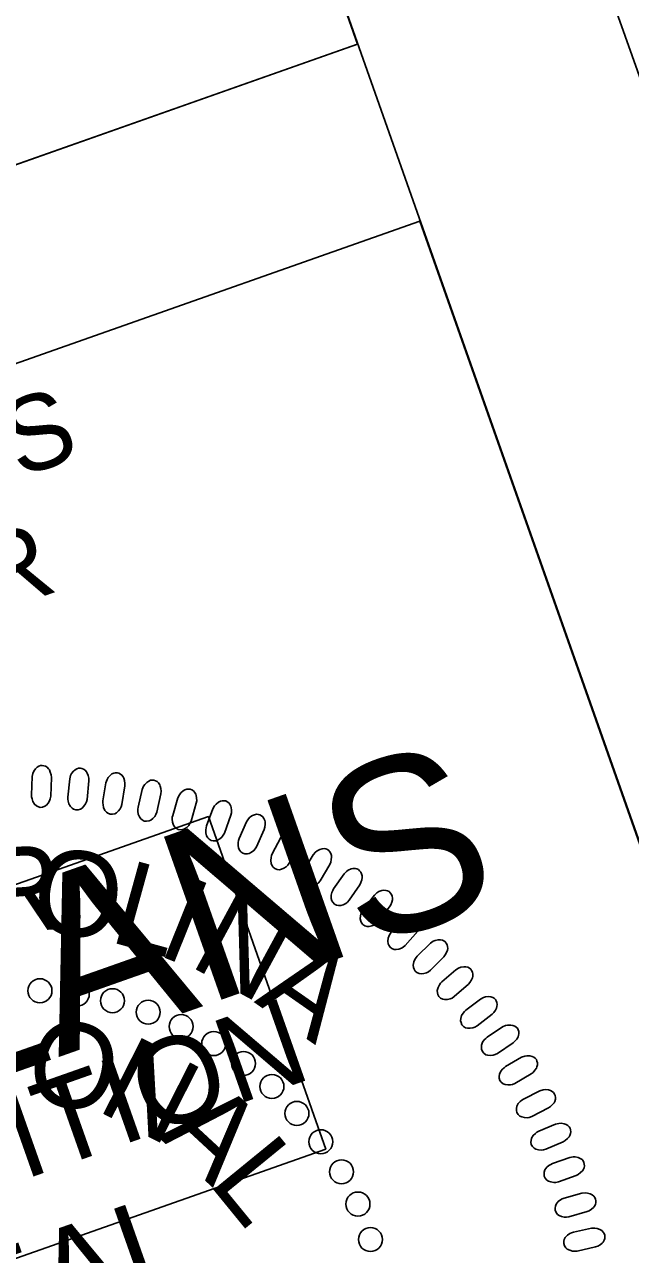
# Model space of a CAD drawing. Extents: x 473817 to 475769, y 501102 to 502694.
# Drawn here: x 475382.8 to 475423.1, y 502563 to 502645 of the extents above; entities that cross this region are included whole.
import ezdxf

# ---------------------------------------------------------------- set-up
doc = ezdxf.new("R2010")
doc.units = 0
for name, color, linetype in [('Sheet PE Seal Cell', 7, 'Continuous'), ('Sheet Plan CELL', 7, 'Continuous'), ('Sheet Plot Border Outside CELL', 7, 'Continuous'), ('Sheet Sticker Incomplete CELL', 7, 'Continuous')]:
    doc.layers.add(name, color=color, linetype=linetype)

msp = doc.modelspace()

# ---------------------------------------------------------------- linework, layer by layer
at = {"layer": 'Sheet PE Seal Cell'}
for points in [[(475383.217, 502593.623), (475383.264, 502594.848), (475383.31, 502595.066), (475383.367, 502595.204), (475383.486, 502595.369), (475383.588, 502595.475), (475383.703, 502595.55), (475383.809, 502595.586), (475383.921, 502595.602), (475384.032, 502595.578), (475384.151, 502595.543), (475384.253, 502595.479), (475384.354, 502595.375), (475384.411, 502595.294), (475384.472, 502595.142), (475384.526, 502594.96), (475384.542, 502594.8), (475384.501, 502593.543), (475384.472, 502593.375), (475384.422, 502593.237), (475384.326, 502593.082), (475384.209, 502592.946), (475384.109, 502592.87), (475383.949, 502592.817), (475383.799, 502592.802), (475383.651, 502592.848), (475383.548, 502592.901), (475383.425, 502593.006), (475383.313, 502593.18), (475383.252, 502593.362), (475383.227, 502593.493)], [(475385.642, 502593.487), (475385.765, 502594.708), (475385.825, 502594.922), (475385.891, 502595.056), (475386.02, 502595.213), (475386.127, 502595.312), (475386.247, 502595.38), (475386.355, 502595.41), (475386.469, 502595.418), (475386.578, 502595.386), (475386.694, 502595.345), (475386.792, 502595.275), (475386.886, 502595.165), (475386.938, 502595.08), (475386.99, 502594.924), (475387.031, 502594.74), (475387.038, 502594.578), (475386.918, 502593.327), (475386.878, 502593.161), (475386.819, 502593.026), (475386.714, 502592.877), (475386.588, 502592.749), (475386.484, 502592.68), (475386.321, 502592.636), (475386.17, 502592.632), (475386.026, 502592.686), (475385.927, 502592.746), (475385.811, 502592.858), (475385.709, 502593.039), (475385.66, 502593.224), (475385.644, 502593.356)], [(475387.982, 502593.236), (475388.182, 502594.446), (475388.255, 502594.656), (475388.329, 502594.786), (475388.468, 502594.934), (475388.581, 502595.027), (475388.706, 502595.087), (475388.815, 502595.11), (475388.929, 502595.111), (475389.036, 502595.073), (475389.149, 502595.024), (475389.243, 502594.948), (475389.33, 502594.833), (475389.376, 502594.744), (475389.418, 502594.586), (475389.447, 502594.398), (475389.444, 502594.238), (475389.246, 502592.996), (475389.196, 502592.833), (475389.129, 502592.702), (475389.015, 502592.56), (475388.881, 502592.44), (475388.772, 502592.377), (475388.607, 502592.344), (475388.457, 502592.349), (475388.316, 502592.412), (475388.22, 502592.479), (475388.111, 502592.598), (475388.021, 502592.785), (475387.984, 502592.973), (475387.976, 502593.106)], [(475390.317, 502592.803), (475390.593, 502593.998), (475390.679, 502594.203), (475390.761, 502594.327), (475390.908, 502594.468), (475391.028, 502594.553), (475391.155, 502594.605), (475391.266, 502594.62), (475391.38, 502594.615), (475391.485, 502594.57), (475391.594, 502594.514), (475391.683, 502594.433), (475391.763, 502594.311), (475391.803, 502594.22), (475391.835, 502594.059), (475391.853, 502593.871), (475391.839, 502593.711), (475391.563, 502592.484), (475391.503, 502592.324), (475391.428, 502592.199), (475391.305, 502592.063), (475391.165, 502591.952), (475391.052, 502591.896), (475390.885, 502591.873), (475390.735, 502591.888), (475390.599, 502591.96), (475390.508, 502592.032), (475390.406, 502592.158), (475390.328, 502592.35), (475390.303, 502592.54), (475390.303, 502592.673)], [(475392.627, 502592.267), (475392.977, 502593.442), (475393.075, 502593.643), (475393.166, 502593.762), (475393.321, 502593.892), (475393.446, 502593.969), (475393.576, 502594.014), (475393.688, 502594.022), (475393.801, 502594.009), (475393.903, 502593.958), (475394.008, 502593.895), (475394.092, 502593.808), (475394.164, 502593.682), (475394.199, 502593.589), (475394.22, 502593.426), (475394.226, 502593.237), (475394.202, 502593.078), (475393.85, 502591.871), (475393.78, 502591.715), (475393.697, 502591.594), (475393.566, 502591.467), (475393.419, 502591.365), (475393.302, 502591.316), (475393.135, 502591.304), (475392.986, 502591.328), (475392.854, 502591.408), (475392.768, 502591.486), (475392.675, 502591.618), (475392.609, 502591.815), (475392.596, 502592.006), (475392.604, 502592.139)], [(475394.884, 502591.561), (475395.308, 502592.713), (475395.418, 502592.906), (475395.516, 502593.019), (475395.68, 502593.14), (475395.809, 502593.209), (475395.941, 502593.245), (475396.053, 502593.246), (475396.166, 502593.226), (475396.264, 502593.169), (475396.366, 502593.099), (475396.443, 502593.007), (475396.507, 502592.877), (475396.536, 502592.782), (475396.547, 502592.618), (475396.541, 502592.429), (475396.508, 502592.272), (475396.081, 502591.09), (475396.001, 502590.938), (475395.911, 502590.822), (475395.772, 502590.704), (475395.618, 502590.611), (475395.499, 502590.57), (475395.331, 502590.568), (475395.184, 502590.601), (475395.057, 502590.69), (475394.976, 502590.773), (475394.892, 502590.911), (475394.838, 502591.11), (475394.837, 502591.303), (475394.854, 502591.435)], [(475397.058, 502590.722), (475397.554, 502591.845), (475397.676, 502592.031), (475397.78, 502592.138), (475397.951, 502592.248), (475398.085, 502592.309), (475398.219, 502592.337), (475398.331, 502592.331), (475398.442, 502592.304), (475398.536, 502592.24), (475398.634, 502592.165), (475398.706, 502592.068), (475398.761, 502591.934), (475398.784, 502591.837), (475398.785, 502591.673), (475398.767, 502591.485), (475398.723, 502591.33), (475398.223, 502590.177), (475398.134, 502590.031), (475398.037, 502589.921), (475397.89, 502589.812), (475397.732, 502589.729), (475397.61, 502589.695), (475397.442, 502589.703), (475397.297, 502589.746), (475397.177, 502589.843), (475397.101, 502589.93), (475397.025, 502590.073), (475396.984, 502590.276), (475396.995, 502590.467), (475397.02, 502590.598)], [(475399.267, 502589.706), (475399.831, 502590.795), (475399.965, 502590.972), (475400.076, 502591.073), (475400.253, 502591.171), (475400.39, 502591.224), (475400.526, 502591.243), (475400.638, 502591.231), (475400.747, 502591.197), (475400.837, 502591.127), (475400.93, 502591.046), (475400.995, 502590.945), (475401.042, 502590.808), (475401.058, 502590.709), (475401.049, 502590.546), (475401.02, 502590.359), (475400.966, 502590.207), (475400.394, 502589.088), (475400.297, 502588.948), (475400.193, 502588.844), (475400.04, 502588.744), (475399.876, 502588.671), (475399.752, 502588.645), (475399.586, 502588.664), (475399.444, 502588.715), (475399.329, 502588.819), (475399.26, 502588.912), (475399.192, 502589.059), (475399.165, 502589.264), (475399.187, 502589.455), (475399.221, 502589.584)], [(475401.368, 502588.595), (475401.999, 502589.646), (475402.145, 502589.815), (475402.261, 502589.908), (475402.445, 502589.996), (475402.585, 502590.04), (475402.722, 502590.05), (475402.832, 502590.03), (475402.939, 502589.99), (475403.024, 502589.915), (475403.111, 502589.828), (475403.171, 502589.723), (475403.209, 502589.583), (475403.219, 502589.484), (475403.199, 502589.321), (475403.158, 502589.137), (475403.095, 502588.988), (475402.454, 502587.907), (475402.348, 502587.773), (475402.238, 502587.677), (475402.079, 502587.587), (475401.911, 502587.524), (475401.786, 502587.506), (475401.621, 502587.535), (475401.482, 502587.595), (475401.375, 502587.706), (475401.311, 502587.803), (475401.253, 502587.954), (475401.238, 502588.161), (475401.273, 502588.35), (475401.314, 502588.476)], [(475403.351, 502587.362), (475404.048, 502588.371), (475404.203, 502588.531), (475404.325, 502588.616), (475404.514, 502588.692), (475404.656, 502588.727), (475404.793, 502588.729), (475404.902, 502588.703), (475405.006, 502588.655), (475405.087, 502588.575), (475405.168, 502588.483), (475405.221, 502588.374), (475405.25, 502588.233), (475405.254, 502588.133), (475405.224, 502587.971), (475405.172, 502587.79), (475405.1, 502587.646), (475404.392, 502586.607), (475404.278, 502586.481), (475404.161, 502586.391), (475403.997, 502586.311), (475403.825, 502586.259), (475403.7, 502586.249), (475403.537, 502586.288), (475403.402, 502586.357), (475403.302, 502586.475), (475403.245, 502586.575), (475403.196, 502586.729), (475403.194, 502586.937), (475403.24, 502587.123), (475403.29, 502587.247)], [(475405.319, 502585.992), (475406.077, 502586.956), (475406.243, 502587.106), (475406.37, 502587.183), (475406.563, 502587.247), (475406.707, 502587.273), (475406.844, 502587.267), (475406.952, 502587.233), (475407.052, 502587.18), (475407.128, 502587.095), (475407.203, 502586.997), (475407.248, 502586.886), (475407.269, 502586.742), (475407.267, 502586.642), (475407.227, 502586.483), (475407.163, 502586.305), (475407.082, 502586.166), (475406.311, 502585.174), (475406.189, 502585.055), (475406.067, 502584.973), (475405.898, 502584.903), (475405.723, 502584.862), (475405.597, 502584.859), (475405.437, 502584.909), (475405.308, 502584.986), (475405.215, 502585.11), (475405.163, 502585.214), (475405.125, 502585.371), (475405.135, 502585.578), (475405.194, 502585.761), (475405.251, 502585.881)], [(475407.19, 502584.478), (475408.008, 502585.393), (475408.182, 502585.531), (475408.313, 502585.601), (475408.51, 502585.653), (475408.655, 502585.67), (475408.793, 502585.654), (475408.897, 502585.614), (475408.994, 502585.554), (475409.064, 502585.465), (475409.133, 502585.363), (475409.172, 502585.249), (475409.183, 502585.104), (475409.175, 502585.005), (475409.125, 502584.848), (475409.05, 502584.675), (475408.96, 502584.541), (475408.129, 502583.599), (475407.999, 502583.488), (475407.872, 502583.413), (475407.699, 502583.355), (475407.523, 502583.325), (475407.397, 502583.33), (475407.24, 502583.39), (475407.115, 502583.475), (475407.03, 502583.604), (475406.985, 502583.711), (475406.957, 502583.87), (475406.981, 502584.077), (475407.051, 502584.255), (475407.115, 502584.372)], [(475408.927, 502582.882), (475409.8, 502583.744), (475409.983, 502583.871), (475410.119, 502583.932), (475410.318, 502583.971), (475410.465, 502583.978), (475410.601, 502583.955), (475410.702, 502583.909), (475410.795, 502583.842), (475410.86, 502583.749), (475410.922, 502583.642), (475410.953, 502583.526), (475410.956, 502583.382), (475410.941, 502583.283), (475410.882, 502583.129), (475410.795, 502582.962), (475410.698, 502582.833), (475409.808, 502581.945), (475409.672, 502581.843), (475409.541, 502581.777), (475409.365, 502581.729), (475409.186, 502581.71), (475409.061, 502581.723), (475408.908, 502581.793), (475408.789, 502581.886), (475408.713, 502582.02), (475408.675, 502582.13), (475408.656, 502582.29), (475408.693, 502582.494), (475408.774, 502582.668), (475408.846, 502582.78)], [(475410.569, 502581.169), (475411.495, 502581.975), (475411.685, 502582.09), (475411.824, 502582.143), (475412.026, 502582.169), (475412.173, 502582.167), (475412.307, 502582.135), (475412.405, 502582.083), (475412.494, 502582.011), (475412.552, 502581.913), (475412.608, 502581.803), (475412.632, 502581.686), (475412.625, 502581.54), (475412.605, 502581.443), (475412.536, 502581.294), (475412.44, 502581.131), (475412.334, 502581.01), (475411.39, 502580.18), (475411.248, 502580.085), (475411.113, 502580.028), (475410.934, 502579.991), (475410.755, 502579.983), (475410.63, 502580.005), (475410.482, 502580.084), (475410.369, 502580.184), (475410.301, 502580.323), (475410.27, 502580.434), (475410.262, 502580.596), (475410.312, 502580.797), (475410.403, 502580.966), (475410.482, 502581.073)], [(475412.163, 502579.278), (475413.138, 502580.023), (475413.335, 502580.126), (475413.478, 502580.17), (475413.68, 502580.184), (475413.827, 502580.174), (475413.958, 502580.133), (475414.053, 502580.074), (475414.137, 502579.997), (475414.189, 502579.896), (475414.238, 502579.782), (475414.254, 502579.663), (475414.238, 502579.519), (475414.212, 502579.423), (475414.133, 502579.278), (475414.028, 502579.122), (475413.914, 502579.007), (475412.921, 502578.238), (475412.772, 502578.153), (475412.634, 502578.105), (475412.453, 502578.079), (475412.274, 502578.082), (475412.151, 502578.111), (475412.008, 502578.199), (475411.902, 502578.306), (475411.843, 502578.45), (475411.819, 502578.562), (475411.821, 502578.725), (475411.883, 502578.922), (475411.984, 502579.085), (475412.069, 502579.187)], [(475413.588, 502577.476), (475414.608, 502578.158), (475414.81, 502578.249), (475414.956, 502578.284), (475415.159, 502578.285), (475415.305, 502578.266), (475415.433, 502578.216), (475415.524, 502578.152), (475415.603, 502578.07), (475415.649, 502577.965), (475415.691, 502577.849), (475415.7, 502577.73), (475415.675, 502577.587), (475415.642, 502577.492), (475415.555, 502577.354), (475415.439, 502577.203), (475415.319, 502577.096), (475414.279, 502576.391), (475414.125, 502576.316), (475413.984, 502576.275), (475413.802, 502576.261), (475413.624, 502576.276), (475413.503, 502576.312), (475413.366, 502576.41), (475413.266, 502576.523), (475413.217, 502576.669), (475413.2, 502576.784), (475413.212, 502576.945), (475413.286, 502577.138), (475413.398, 502577.294), (475413.489, 502577.391)], [(475414.819, 502575.52), (475415.879, 502576.136), (475416.087, 502576.214), (475416.234, 502576.24), (475416.437, 502576.228), (475416.58, 502576.199), (475416.707, 502576.143), (475416.793, 502576.072), (475416.867, 502575.986), (475416.906, 502575.879), (475416.94, 502575.76), (475416.941, 502575.64), (475416.908, 502575.499), (475416.869, 502575.407), (475416.773, 502575.273), (475416.648, 502575.132), (475416.522, 502575.032), (475415.439, 502574.393), (475415.281, 502574.327), (475415.139, 502574.296), (475414.955, 502574.294), (475414.779, 502574.32), (475414.661, 502574.364), (475414.529, 502574.469), (475414.437, 502574.589), (475414.397, 502574.738), (475414.387, 502574.853), (475414.409, 502575.013), (475414.496, 502575.201), (475414.617, 502575.351), (475414.714, 502575.441)], [(475416.005, 502573.352), (475417.102, 502573.9), (475417.315, 502573.965), (475417.463, 502573.982), (475417.665, 502573.957), (475417.807, 502573.92), (475417.928, 502573.855), (475418.011, 502573.78), (475418.078, 502573.688), (475418.111, 502573.579), (475418.138, 502573.458), (475418.132, 502573.338), (475418.089, 502573.2), (475418.045, 502573.111), (475417.941, 502572.983), (475417.807, 502572.849), (475417.674, 502572.758), (475416.554, 502572.188), (475416.392, 502572.133), (475416.247, 502572.11), (475416.065, 502572.119), (475415.89, 502572.157), (475415.775, 502572.208), (475415.651, 502572.321), (475415.566, 502572.447), (475415.535, 502572.598), (475415.533, 502572.714), (475415.565, 502572.872), (475415.663, 502573.055), (475415.794, 502573.195), (475415.896, 502573.28)], [(475417.021, 502571.202), (475418.151, 502571.681), (475418.367, 502571.732), (475418.516, 502571.74), (475418.716, 502571.703), (475418.855, 502571.656), (475418.972, 502571.584), (475419.049, 502571.503), (475419.112, 502571.408), (475419.137, 502571.297), (475419.156, 502571.175), (475419.142, 502571.055), (475419.091, 502570.92), (475419.041, 502570.834), (475418.93, 502570.713), (475418.788, 502570.588), (475418.65, 502570.505), (475417.496, 502570.007), (475417.331, 502569.962), (475417.185, 502569.949), (475417.003, 502569.969), (475416.831, 502570.017), (475416.72, 502570.075), (475416.603, 502570.196), (475416.526, 502570.327), (475416.505, 502570.479), (475416.51, 502570.596), (475416.552, 502570.751), (475416.661, 502570.927), (475416.8, 502571.06), (475416.908, 502571.138)], [(475417.937, 502569.054), (475419.094, 502569.462), (475419.313, 502569.499), (475419.462, 502569.497), (475419.66, 502569.447), (475419.796, 502569.392), (475419.908, 502569.312), (475419.98, 502569.227), (475420.036, 502569.128), (475420.055, 502569.015), (475420.066, 502568.893), (475420.044, 502568.774), (475419.985, 502568.642), (475419.93, 502568.56), (475419.811, 502568.446), (475419.662, 502568.33), (475419.519, 502568.256), (475418.336, 502567.831), (475418.169, 502567.796), (475418.022, 502567.793), (475417.841, 502567.824), (475417.673, 502567.883), (475417.565, 502567.948), (475417.456, 502568.077), (475417.388, 502568.211), (475417.376, 502568.365), (475417.388, 502568.48), (475417.44, 502568.634), (475417.561, 502568.803), (475417.707, 502568.926), (475417.82, 502568.997)], [(475418.717, 502566.741), (475419.898, 502567.076), (475420.118, 502567.099), (475420.267, 502567.087), (475420.462, 502567.026), (475420.594, 502566.962), (475420.7, 502566.876), (475420.767, 502566.786), (475420.817, 502566.683), (475420.828, 502566.57), (475420.832, 502566.447), (475420.803, 502566.33), (475420.735, 502566.202), (475420.675, 502566.123), (475420.549, 502566.017), (475420.393, 502565.911), (475420.245, 502565.846), (475419.038, 502565.496), (475418.87, 502565.472), (475418.723, 502565.477), (475418.545, 502565.52), (475418.38, 502565.59), (475418.276, 502565.661), (475418.176, 502565.796), (475418.116, 502565.935), (475418.114, 502566.089), (475418.134, 502566.204), (475418.195, 502566.353), (475418.325, 502566.514), (475418.48, 502566.628), (475418.596, 502566.691)], [(475419.338, 502564.48), (475420.538, 502564.739), (475420.76, 502564.749), (475420.907, 502564.727), (475421.097, 502564.654), (475421.225, 502564.582), (475421.326, 502564.489), (475421.387, 502564.395), (475421.43, 502564.289), (475421.435, 502564.176), (475421.43, 502564.052), (475421.394, 502563.938), (475421.319, 502563.815), (475421.254, 502563.739), (475421.122, 502563.642), (475420.959, 502563.546), (475420.808, 502563.49), (475419.581, 502563.217), (475419.41, 502563.203), (475419.264, 502563.217), (475419.09, 502563.271), (475418.929, 502563.351), (475418.831, 502563.429), (475418.739, 502563.57), (475418.688, 502563.712), (475418.696, 502563.867), (475418.722, 502563.979), (475418.792, 502564.125), (475418.933, 502564.277), (475419.095, 502564.381), (475419.215, 502564.437)]]:
    msp.add_lwpolyline(points, close=True, dxfattribs=at)
for centre in [(475383.781, 502580.574), (475386.266, 502580.351), (475388.615, 502579.911), (475390.996, 502579.145), (475393.191, 502578.186), (475395.364, 502577.051), (475397.351, 502575.724), (475399.241, 502574.193), (475400.906, 502572.395), (475402.499, 502570.507), (475403.881, 502568.502), (475404.975, 502566.353), (475405.809, 502563.986)]:
    msp.add_circle(centre, 0.801, dxfattribs=at)
at = {"layer": 'Sheet Plan CELL'}
msp.add_line((475216.297, 502577.132), (475404.942, 502643.676), dxfattribs=at)
msp.add_line((475216.297, 502577.132), (475404.942, 502643.676), dxfattribs=at)
for points in [[(475396.647, 502667.313), (473981.977, 502168.491), (474331.144, 501178.248), (475745.79, 501677.061)], [(475207.954, 502600.792), (475396.647, 502667.313), (475404.942, 502643.676), (475216.297, 502577.132)], [(475314.805, 502598.626), (475409.098, 502631.888), (475446.525, 502525.783), (475352.22, 502492.517)]]:
    msp.add_lwpolyline(points, close=True, dxfattribs=at)
at = {"layer": 'Sheet Plot Border Outside CELL'}
msp.add_lwpolyline([(474181.618, 501101.653), (475769.309, 501661.483), (475405.178, 502694.166), (473817.487, 502134.335)], close=True, dxfattribs=at)
at = {"layer": 'Sheet Sticker Incomplete CELL'}
msp.add_lwpolyline([(475264.194, 502521.136), (475256.379, 502543.298), (475395.013, 502592.182), (475402.828, 502570.019)], close=True, dxfattribs=at)

# ---------------------------------------------------------------- texts
at = {"layer": 'Sheet PE Seal Cell'}
for s, height, rotation, p in [('R', 5.669, 4.03196, (475379.981, 502584.328)), ('O', 5.669, 351.05324, (475382.985, 502584.694)), ('L', 5.669, 344.56389, (475388.29, 502583.881)), ('I', 5.669, 338.07453, (475391.446, 502583.029)), ('N', 5.669, 331.58517, (475393.621, 502582.29)), ('A', 5.669, 325.09581, (475398.009, 502579.829)), ('O', 5.669, 348.95283, (475382.61, 502573.388)), ('N', 5.669, 333.07324, (475387.443, 502572.648)), ('A', 5.669, 317.19364, (475391.615, 502570.853)), ('L', 5.669, 309.25385, (475394.946, 502567.791)), ('SEAL', 6.2363, 19.40435, (475374.413, 502554.389))]:
    msp.add_text(s, height=height, rotation=rotation, dxfattribs=at).set_placement(p)
at = {"layer": 'Sheet Plan CELL'}
for s, p in [('HYDRAULICS', (475345.953, 502601.895)), ('ENGINEER', (475352.15, 502595.637))]:
    msp.add_text(s, height=5.0001, rotation=19.42299, dxfattribs=at).set_placement(p)
at = {"layer": 'Sheet Sticker Incomplete CELL'}
for s, height, p in [('INCOMPLETE PLANS', 11.52, (475268.744, 502535.146)), ('DO NOT USE FOR R/W ACQUISITION', 5.76, (475274.12, 502529.672))]:
    msp.add_text(s, height=height, rotation=19.42299, dxfattribs=at).set_placement(p)

doc.saveas('drawing.dxf')
